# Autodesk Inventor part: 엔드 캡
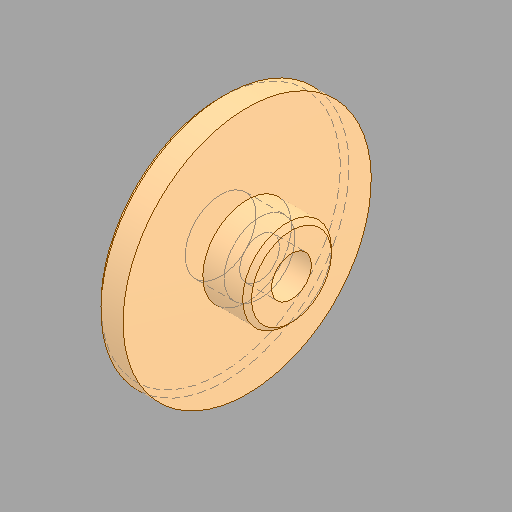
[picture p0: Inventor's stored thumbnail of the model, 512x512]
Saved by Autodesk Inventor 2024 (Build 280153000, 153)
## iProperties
Created: 2025-11
Part Number: 엔드 캡
Material: 강철, 연강
Document SubType Name: Modeling
Designer: Edu09
Density: 7.85 g/cm^3
Appearance: 기본값
Author: jhkim
Sending System: Autodesk Inventor 2026
Preprocessor: ST-DEVELOPER v20.1
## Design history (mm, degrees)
feature "솔리드1"
node "솔리드2"
